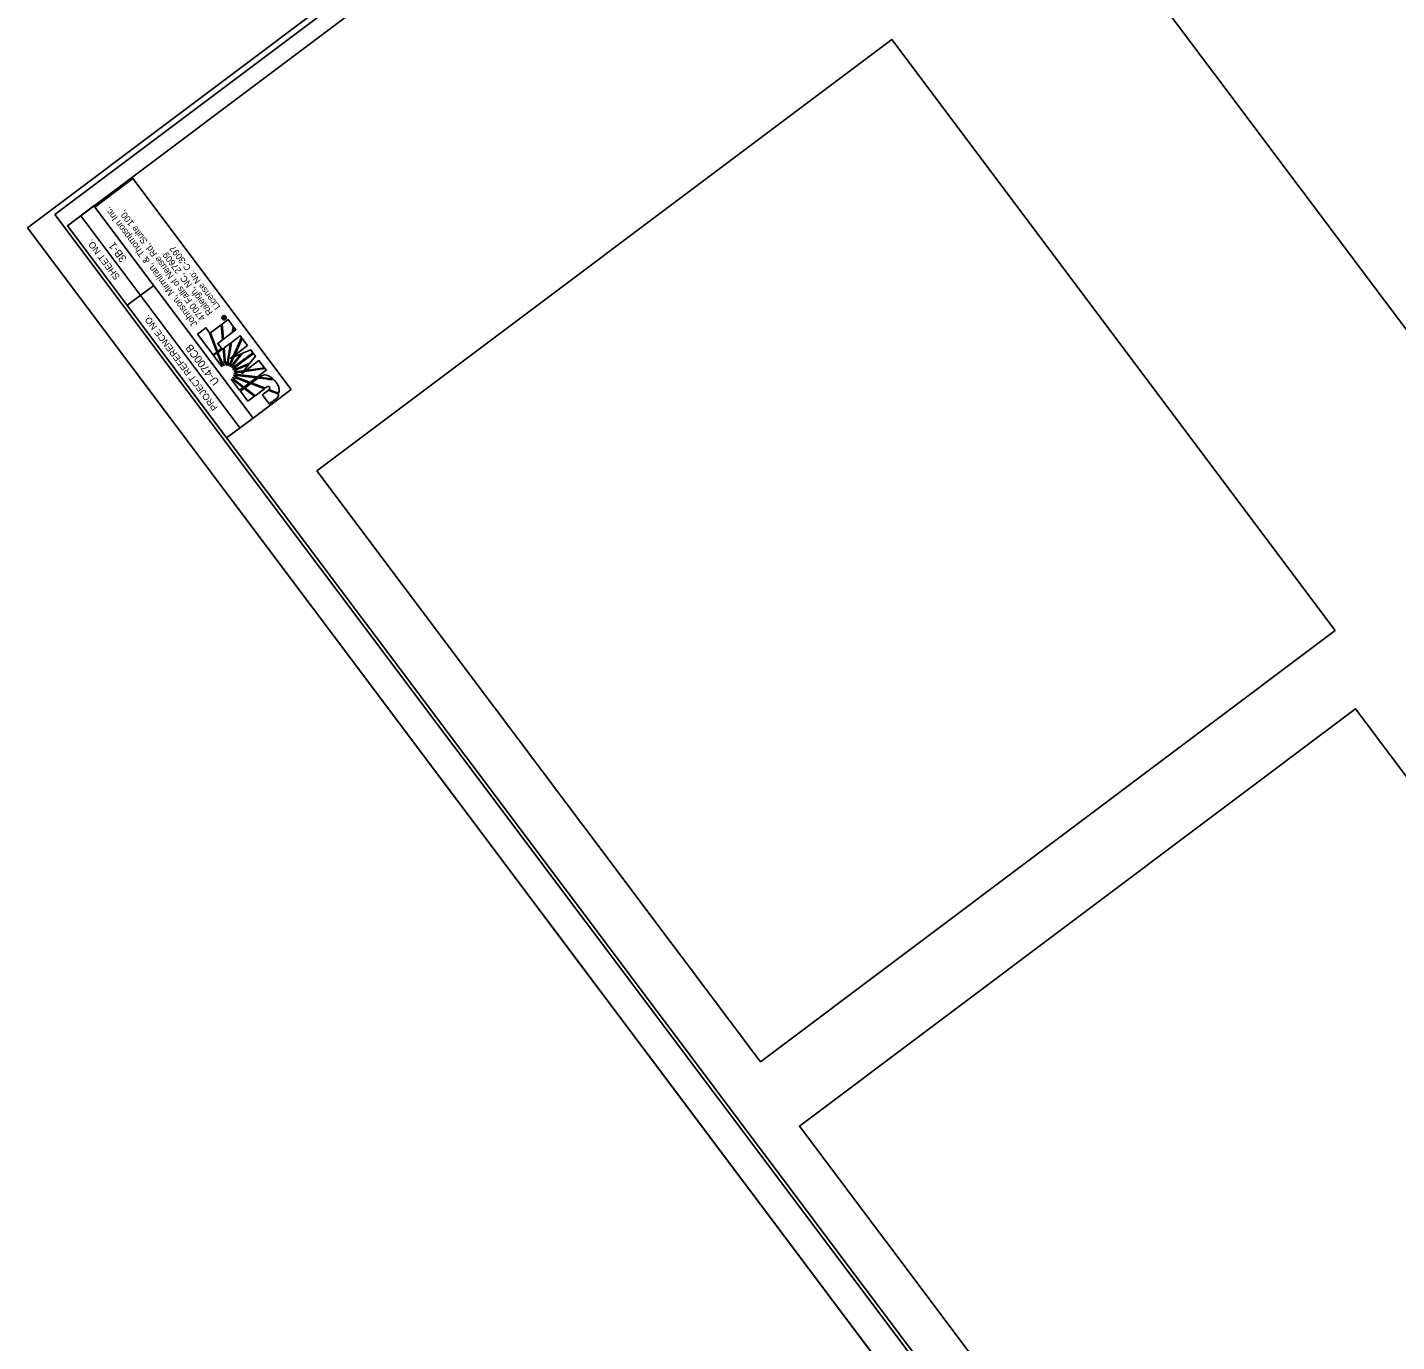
# Model space of a CAD drawing. Extents: x -35.4 to 7.5, y -22.3 to 27.3.
# Drawn here: x -35.41 to -14.76, y -5.44 to 14.38 of the extents above; entities that cross this region are included whole.
import ezdxf

# ---------------------------------------------------------------- set-up
doc = ezdxf.new("R2010")
doc.units = 0
for name, color, linetype in [('Default', 7, 'Continuous'), ('Sheet Cutting Line CELL', 7, 'Continuous'), ('Sheet Data Field CELL', 7, 'Continuous'), ('Sheet Plot Border Inside CELL', 7, 'Continuous'), ('Sheet Plot Border Outside CELL', 7, 'Continuous'), ('Sheet Summary Combination CELL', 7, 'Continuous')]:
    doc.layers.add(name, color=color, linetype=linetype)

msp = doc.modelspace()

# ---------------------------------------------------------------- linework, layer by layer
at = {"layer": 'Default'}
for points in [[(-0.077, -0.055), (-18.097, 23.955), (-22.648, 20.539), (-4.628, -3.47)], [(-15.68, 5.289), (-22.37, 14.202), (-31.04, 7.695), (-24.35, -1.218)], [(-8.847, -4.589), (-15.374, 4.108), (-23.763, -2.188), (-17.236, -10.885)]]:
    msp.add_lwpolyline(points, close=True, dxfattribs=at)
at = {"layer": 'Sheet Cutting Line CELL'}
msp.add_line((-35.408, 11.363), (-15.19, -15.574), dxfattribs=at)
at = {"layer": 'Sheet Data Field CELL'}
for p, q in [((-32.379, 9.976), (-32.471, 9.907)), ((-32.465, 9.987), (-32.461, 9.991)), ((-32.461, 9.991), (-32.465, 9.987)), ((-32.452, 9.997), (-32.453, 9.999)), ((-32.452, 9.997), (-32.448, 10)), ((-32.448, 10), (-32.452, 9.997)), ((-32.445, 9.988), (-32.452, 9.997)), ((-32.448, 10.001), (-32.448, 10)), ((-32.448, 10), (-32.444, 9.996)), ((-32.422, 10.005), (-32.445, 9.988)), ((-32.444, 9.996), (-32.439, 10)), ((-32.442, 10.004), (-32.438, 10.008)), ((-32.438, 10.008), (-32.442, 10.004)), ((-32.442, 10.004), (-32.442, 10.005)), ((-32.439, 10), (-32.442, 10.004)), ((-32.438, 10.008), (-32.435, 10.003)), ((-32.438, 10.008), (-32.438, 10.008)), ((-32.435, 10.003), (-32.426, 10.01)), ((-32.426, 10.01), (-32.422, 10.005)), ((-32.42, 10.021), (-32.415, 10.025)), ((-32.415, 10.025), (-32.42, 10.021)), ((-32.42, 10.021), (-32.42, 10.021)), ((-32.415, 10.025), (-32.415, 10.025)), ((-32.303, 9.875), (-32.379, 9.976)), ((-32.714, 9.853), (-32.842, 9.756)), ((-32.842, 9.756), (-32.607, 9.444)), ((-32.664, 9.786), (-32.714, 9.853)), ((-32.548, 9.488), (-32.664, 9.786)), ((-32.483, 9.898), (-32.647, 9.775)), ((-32.647, 9.775), (-32.539, 9.495)), ((-32.464, 9.671), (-32.483, 9.898)), ((-32.471, 9.907), (-32.452, 9.68)), ((-32.452, 9.68), (-32.319, 9.78)), ((-32.196, 9.733), (-32.329, 9.633)), ((-32.319, 9.78), (-32.303, 9.875)), ((-32.292, 9.861), (-32.304, 9.791)), ((-32.304, 9.791), (-32.263, 9.822)), ((-32.302, 9.426), (-32.176, 9.707)), ((-32.263, 9.822), (-32.292, 9.861)), ((-32.176, 9.707), (-32.196, 9.733)), ((-32.538, 9.495), (-32.478, 9.541)), ((-32.536, 9.617), (-32.464, 9.671)), ((-32.478, 9.541), (-32.536, 9.617)), ((-32.453, 9.54), (-32.533, 9.481)), ((-32.439, 9.378), (-32.453, 9.54)), ((-32.345, 9.621), (-32.44, 9.55)), ((-32.44, 9.55), (-32.425, 9.361)), ((-32.391, 9.341), (-32.345, 9.621)), ((-32.329, 9.633), (-32.379, 9.34)), ((-32.168, 9.694), (-32.281, 9.442)), ((-32.281, 9.442), (-32.088, 9.588)), ((-32.088, 9.588), (-32.168, 9.694)), ((-32.036, 9.519), (-32.162, 9.469)), ((-32.005, 9.477), (-32.036, 9.519)), ((-32.607, 9.444), (-32.55, 9.487)), ((-32.544, 9.473), (-32.598, 9.433)), ((-32.598, 9.433), (-32.474, 9.267)), ((-32.55, 9.487), (-32.548, 9.488)), ((-32.486, 9.324), (-32.544, 9.473)), ((-32.539, 9.495), (-32.538, 9.495)), ((-32.533, 9.481), (-32.472, 9.328)), ((-32.474, 9.267), (-32.486, 9.324)), ((-32.472, 9.328), (-32.444, 9.277)), ((-32.444, 9.277), (-32.439, 9.378)), ((-32.425, 9.361), (-32.411, 9.282)), ((-32.411, 9.282), (-32.391, 9.341)), ((-32.379, 9.34), (-32.38, 9.278)), ((-32.38, 9.278), (-32.346, 9.332)), ((-32.334, 9.324), (-32.351, 9.266)), ((-32.351, 9.266), (-32.307, 9.307)), ((-32.346, 9.393), (-32.302, 9.426)), ((-32.346, 9.332), (-32.311, 9.408)), ((-32.311, 9.408), (-32.346, 9.393)), ((-32.294, 9.415), (-32.334, 9.324)), ((-32.326, 9.248), (-32.203, 9.328)), ((-32.293, 9.303), (-32.326, 9.248)), ((-32.195, 9.318), (-32.308, 9.223)), ((-32.307, 9.307), (-32.185, 9.459)), ((-32.185, 9.459), (-32.294, 9.415)), ((-32.162, 9.469), (-32.293, 9.303)), ((-32.069, 9.297), (-32.247, 9.224)), ((-32.245, 9.239), (-32.052, 9.317)), ((-32.203, 9.328), (-32.005, 9.477)), ((-31.997, 9.467), (-32.195, 9.318)), ((-32.141, 9.206), (-32.069, 9.297)), ((-31.915, 9.359), (-32.112, 9.209)), ((-32.052, 9.317), (-31.966, 9.426)), ((-31.966, 9.426), (-31.997, 9.467)), ((-31.831, 9.248), (-31.915, 9.359)), ((-32.215, 9.078), (-32.312, 9.102)), ((-32.312, 9.102), (-32.269, 9.058)), ((-32.308, 9.223), (-32.245, 9.239)), ((-32.236, 9.133), (-32.298, 9.132)), ((-32.298, 9.132), (-32.227, 9.096)), ((-32.247, 9.224), (-32.296, 9.194)), ((-32.296, 9.194), (-32.236, 9.193)), ((-32.232, 9.18), (-32.293, 9.162)), ((-32.293, 9.162), (-32.233, 9.146)), ((-32.236, 9.193), (-32.141, 9.206)), ((-31.955, 9.099), (-32.236, 9.133)), ((-32.233, 9.146), (-31.939, 9.111)), ((-32.152, 9.191), (-32.232, 9.18)), ((-32.227, 9.096), (-32.048, 9.029)), ((-32.134, 9.193), (-32.173, 9.164)), ((-32.173, 9.164), (-32.152, 9.191)), ((-31.823, 9.237), (-32.134, 9.193)), ((-32.112, 9.209), (-31.831, 9.248)), ((-32.048, 9.029), (-31.955, 9.099)), ((-31.939, 9.111), (-31.804, 9.212)), ((-31.804, 9.212), (-31.823, 9.237)), ((-32.281, 9.049), (-32.332, 9.078)), ((-32.332, 9.078), (-32.206, 8.91)), ((-32.153, 8.95), (-32.281, 9.049)), ((-32.269, 9.058), (-32.141, 8.959)), ((-32.061, 9.019), (-32.215, 9.078)), ((-32.206, 8.91), (-32.153, 8.95)), ((-32.136, 8.938), (-32.194, 8.895)), ((-32.194, 8.895), (-32.082, 8.746)), ((-32.141, 8.959), (-32.061, 9.019)), ((-31.983, 8.821), (-32.136, 8.938)), ((-32.039, 9.011), (-32.125, 8.947)), ((-32.125, 8.947), (-31.972, 8.829)), ((-31.833, 8.933), (-32.039, 9.011)), ((-31.972, 8.829), (-31.833, 8.933)), ((-32.082, 8.746), (-31.983, 8.821))]:
    msp.add_line(p, q, dxfattribs=at)
msp.add_lwpolyline([(-31.427, 8.923), (-33.815, 12.104), (-34.389, 11.673), (-32.001, 8.492)], close=True, dxfattribs=at)
for points in [[(-32.452, 9.68), (-32.319, 9.78), (-32.303, 9.875), (-32.379, 9.976), (-32.471, 9.907), (-32.452, 9.68), (-32.452, 9.68)], [(-32.442, 10.02), (-32.441, 10.021), (-32.44, 10.022), (-32.439, 10.023), (-32.437, 10.025), (-32.434, 10.02)], [(-32.842, 9.756), (-32.607, 9.444), (-32.55, 9.487), (-32.548, 9.488), (-32.664, 9.786), (-32.714, 9.853), (-32.842, 9.756)], [(-32.539, 9.495), (-32.538, 9.495), (-32.478, 9.541), (-32.536, 9.617), (-32.464, 9.671), (-32.483, 9.898), (-32.647, 9.775), (-32.539, 9.495)], [(-32.38, 9.278), (-32.346, 9.332), (-32.311, 9.408), (-32.346, 9.393), (-32.302, 9.426), (-32.176, 9.707), (-32.196, 9.733), (-32.329, 9.633), (-32.379, 9.34), (-32.38, 9.278)], [(-32.263, 9.822), (-32.263, 9.822), (-32.292, 9.861), (-32.304, 9.791), (-32.263, 9.822)], [(-32.444, 9.277), (-32.439, 9.378), (-32.453, 9.54), (-32.533, 9.481), (-32.472, 9.328), (-32.444, 9.277)], [(-32.411, 9.282), (-32.391, 9.341), (-32.345, 9.621), (-32.44, 9.55), (-32.425, 9.361), (-32.411, 9.282)], [(-32.326, 9.248), (-32.203, 9.328), (-32.005, 9.477), (-32.036, 9.519), (-32.162, 9.469), (-32.293, 9.303), (-32.326, 9.248)], [(-32.088, 9.588), (-32.168, 9.694), (-32.281, 9.442), (-32.088, 9.588)], [(-32.486, 9.324), (-32.544, 9.473), (-32.598, 9.433), (-32.474, 9.267), (-32.486, 9.324)], [(-32.351, 9.266), (-32.307, 9.307), (-32.185, 9.459), (-32.294, 9.415), (-32.334, 9.324), (-32.351, 9.266)], [(-32.245, 9.239), (-32.052, 9.317), (-31.966, 9.426), (-31.997, 9.467), (-32.195, 9.318), (-32.308, 9.223), (-32.245, 9.239)], [(-32.296, 9.194), (-32.236, 9.193), (-32.141, 9.206), (-32.069, 9.297), (-32.247, 9.224), (-32.296, 9.194)], [(-31.831, 9.248), (-31.915, 9.359), (-32.112, 9.209), (-31.831, 9.248)], [(-32.141, 8.959), (-32.061, 9.019), (-32.215, 9.078), (-32.312, 9.102), (-32.269, 9.058), (-32.141, 8.959)], [(-32.048, 9.029), (-31.955, 9.099), (-32.236, 9.133), (-32.298, 9.132), (-32.227, 9.096), (-32.048, 9.029)], [(-32.293, 9.162), (-32.233, 9.146), (-31.939, 9.111), (-31.804, 9.212), (-31.823, 9.237), (-32.134, 9.193), (-32.173, 9.164), (-32.152, 9.191), (-32.232, 9.18), (-32.293, 9.162)], [(-32.281, 9.049), (-32.332, 9.078), (-32.206, 8.91), (-32.153, 8.95), (-32.281, 9.049)], [(-31.983, 8.821), (-32.136, 8.938), (-32.194, 8.895), (-32.082, 8.746), (-31.983, 8.821)], [(-31.833, 8.933), (-32.039, 9.011), (-32.125, 8.947), (-31.972, 8.829), (-31.833, 8.933)]]:
    msp.add_lwpolyline(points, dxfattribs=at)
for points, degree in [([(-32.465, 9.987), (-32.471, 9.994), (-32.473, 10.002), (-32.472, 10.01), (-32.471, 10.019), (-32.467, 10.026), (-32.46, 10.031)], 3), ([(-32.42, 10.021), (-32.425, 10.027), (-32.43, 10.03), (-32.437, 10.031), (-32.444, 10.032), (-32.45, 10.03), (-32.456, 10.026), (-32.462, 10.022), (-32.465, 10.016), (-32.466, 10.009), (-32.467, 10.003), (-32.465, 9.996), (-32.461, 9.991)], 3), ([(-32.415, 10.025), (-32.41, 10.018), (-32.408, 10.01), (-32.409, 10.001), (-32.41, 9.993), (-32.415, 9.986), (-32.422, 9.98), (-32.429, 9.975), (-32.436, 9.973), (-32.445, 9.975), (-32.453, 9.976), (-32.46, 9.98), (-32.465, 9.987)], 3), ([(-32.461, 9.991), (-32.456, 9.985), (-32.451, 9.982), (-32.444, 9.981), (-32.437, 9.98), (-32.431, 9.981), (-32.425, 9.985), (-32.42, 9.99), (-32.416, 9.995), (-32.415, 10.002), (-32.414, 10.009), (-32.416, 10.015), (-32.42, 10.021)], 3), ([(-32.46, 10.031), (-32.453, 10.036), (-32.445, 10.038), (-32.436, 10.037), (-32.428, 10.036), (-32.421, 10.032), (-32.415, 10.025)], 3), ([(-32.453, 9.999), (-32.457, 10.004), (-32.457, 10.009), (-32.453, 10.012), (-32.451, 10.014), (-32.448, 10.014), (-32.446, 10.013)], 3), ([(-32.442, 10.005), (-32.445, 10.008), (-32.447, 10.009), (-32.449, 10.007), (-32.451, 10.006), (-32.45, 10.004), (-32.448, 10.001)], 3), ([(-32.446, 10.013), (-32.446, 10.016), (-32.445, 10.018), (-32.442, 10.02)], 2), ([(-32.434, 10.02), (-32.434, 10.019), (-32.435, 10.017), (-32.437, 10.016), (-32.439, 10.015), (-32.44, 10.013), (-32.44, 10.012)], 3), ([(-32.44, 10.012), (-32.44, 10.011), (-32.44, 10.01), (-32.438, 10.008)], 2), ([(-31.757, 8.957), (-31.75, 8.949), (-31.749, 8.937), (-31.764, 8.922), (-31.764, 8.922), (-31.617, 8.865), (-31.617, 8.865), (-31.607, 8.923), (-31.626, 8.992), (-31.66, 9.036), (-31.668, 9.047), (-31.676, 9.056), (-31.688, 9.066), (-31.688, 9.066), (-31.927, 9.096), (-31.927, 9.096), (-31.927, 9.096), (-32.027, 9.021), (-32.027, 9.021), (-32.027, 9.021), (-31.821, 8.943), (-31.821, 8.943), (-31.783, 8.971), (-31.766, 8.97), (-31.757, 8.957)], 3), ([(-31.757, 8.957), (-31.75, 8.949), (-31.749, 8.937), (-31.764, 8.922), (-31.764, 8.922), (-31.617, 8.865), (-31.617, 8.865), (-31.607, 8.923), (-31.626, 8.992), (-31.66, 9.036), (-31.668, 9.047), (-31.676, 9.056), (-31.688, 9.066), (-31.688, 9.066), (-31.927, 9.096), (-31.927, 9.096), (-31.927, 9.096), (-32.027, 9.021), (-32.027, 9.021), (-32.027, 9.021), (-31.821, 8.943), (-31.821, 8.943), (-31.783, 8.971), (-31.766, 8.97), (-31.757, 8.957)], 3), ([(-31.911, 9.108), (-31.911, 9.108), (-31.704, 9.082), (-31.704, 9.082), (-31.761, 9.128), (-31.841, 9.156), (-31.911, 9.108)], 3), ([(-31.865, 8.843), (-31.865, 8.843), (-31.761, 8.705), (-31.761, 8.705), (-31.761, 8.705), (-31.675, 8.77), (-31.675, 8.77), (-31.675, 8.77), (-31.666, 8.777), (-31.666, 8.777), (-31.639, 8.797), (-31.624, 8.822), (-31.618, 8.851), (-31.618, 8.851), (-31.772, 8.913), (-31.774, 8.911), (-31.774, 8.911), (-31.865, 8.843), (-31.865, 8.843)], 3)]:
    msp.add_open_spline(points, degree=degree, dxfattribs=at)
at = {"layer": 'Sheet Plot Border Inside CELL'}
msp.add_lwpolyline([(-34.994, 11.561), (-14.987, -15.096), (1.89, -2.429), (-18.117, 24.228)], close=True, dxfattribs=at)
at = {"layer": 'Sheet Plot Border Outside CELL'}
msp.add_lwpolyline([(-35.408, 11.363), (-15.19, -15.574), (2.405, -2.368), (-17.812, 24.569)], close=True, dxfattribs=at)
at = {"layer": 'Sheet Summary Combination CELL'}
for p, q in [((-32.001, 8.492), (-34.403, 11.692)), ((-32.201, 8.342), (-34.603, 11.542)), ((-33.902, 10.192), (-33.502, 10.493))]:
    msp.add_line(p, q, dxfattribs=at)
for points in [[(-34.804, 11.392), (-16.795, -12.602), (0, 0.003), (-18.008, 23.997)], [(-32.402, 8.192), (-34.804, 11.392), (-34.403, 11.692), (-32.001, 8.492)]]:
    msp.add_lwpolyline(points, close=True, dxfattribs=at)

# ---------------------------------------------------------------- texts
at = {"layer": 'Sheet Data Field CELL'}
for s, height, p in [('Johnson, Mirmiran, & Thompson Inc.', 0.10164, (-32.837, 9.913)), ('4700 Falls of Neuse Rd, Suite 100, ', 0.09873, (-32.718, 10.002)), ('Raleigh, NC, 27609', 0.09873, (-32.605, 10.087)), ('License No: C-3097', 0.09873, (-32.492, 10.172))]:
    msp.add_text(s, height=height, rotation=126.8877, dxfattribs=at).set_placement(p)
at = {"layer": 'Sheet Summary Combination CELL'}
for s, height, p in [('SHEET NO.', 0.1, (-34.006, 10.622)), ('3B-1', 0.1162, (-33.903, 10.897)), ('PROJECT REFERENCE NO.', 0.1, (-32.529, 8.651)), ('U-4700CB', 0.1162, (-32.505, 9.039))]:
    msp.add_text(s, height=height, rotation=126.8893, dxfattribs=at).set_placement(p)

doc.saveas('drawing.dxf')
